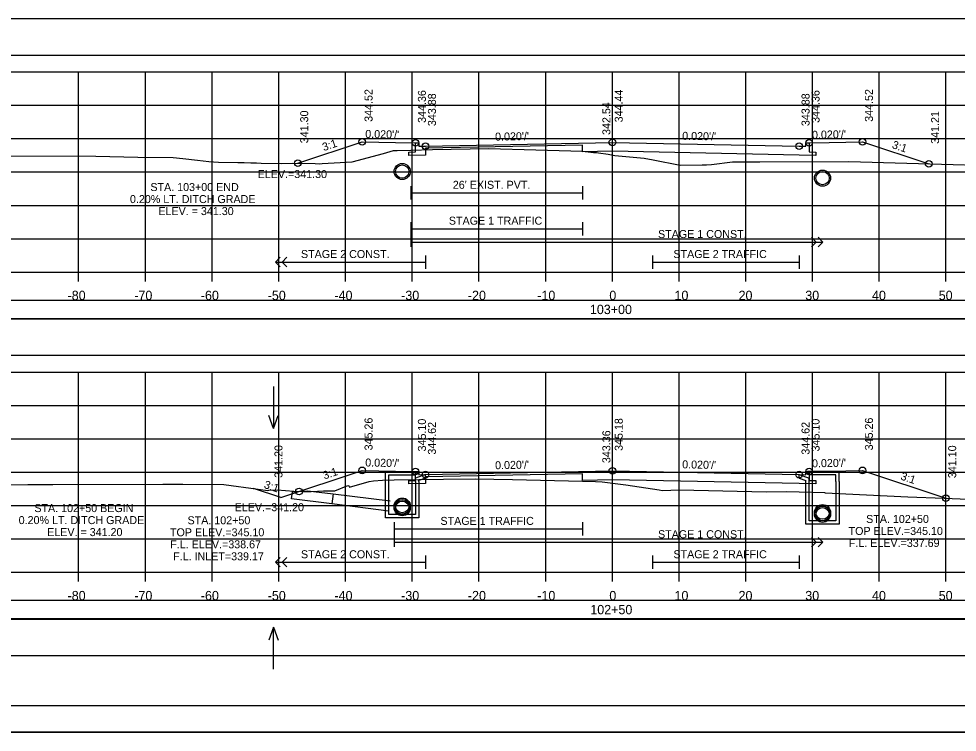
# Model space of a CAD drawing. Extents: x 1368122 to 1710785, y 373130 to 557566.
# Drawn here: x 1368599.9 to 1368740.6, y 373770.3 to 373877.3 of the extents above; entities that cross this region are included whole.
import ezdxf

# ---------------------------------------------------------------- set-up
doc = ezdxf.new("R2010")
doc.units = 0
for name, color, linetype in [('R_Alt Surface', 7, 'Continuous'), ('R_Axis', 7, 'Continuous'), ('R_Axis Annot', 7, 'Continuous'), ('R_Border', 7, 'Continuous'), ('R_Exist Surface', 7, 'Continuous'), ('R_Fin Surface', 7, 'Continuous'), ('R_Grid', 7, 'Continuous'), ('R_No Plot', 7, 'Continuous'), ('R_Striping', 7, 'Continuous'), ('R_Water', 7, 'Continuous'), ('R_Water Annot', 7, 'Continuous'), ('R_Xsect Elev', 7, 'Continuous'), ('R_Xsect Slope', 7, 'Continuous')]:
    doc.layers.add(name, color=color, linetype=linetype)

msp = doc.modelspace()

# ---------------------------------------------------------------- linework, layer by layer
at = {"layer": 'R_Alt Surface'}
for points in [[(1368539.73, 373871.85), (1368838.03, 373871.85), (1368838.03, 373877.26), (1368539.73, 373877.26)], [(1368539.73, 373832.37), (1368838.03, 373832.37), (1368838.03, 373835.08), (1368539.73, 373835.08)], [(1368539.73, 373826.85), (1368838.03, 373826.85), (1368838.03, 373832.26), (1368539.73, 373832.26)], [(1368539.73, 373787.37), (1368838.03, 373787.37), (1368838.03, 373790.08), (1368539.73, 373790.08)], [(1368539.73, 373781.85), (1368838.03, 373781.85), (1368838.03, 373787.26), (1368539.73, 373787.26)]]:
    msp.add_lwpolyline(points, close=True, dxfattribs=at)
for points in [[(1368718.38, 373858.68), (1368718.38, 373857.33), (1368719.38, 373857.31), (1368719.38, 373856.81), (1368716.88, 373856.86), (1368688.88, 373857.43), (1368684.42, 373857.34), (1368684.42, 373858.34), (1368660.88, 373857.87), (1368660.88, 373856.87), (1368660.88, 373856.86), (1368658.38, 373856.81), (1368658.38, 373857.31), (1368659.38, 373857.33), (1368659.38, 373858.68)], [(1368658.66, 373852.2), (1368658.66, 373850.2)], [(1368684.42, 373852.2), (1368684.42, 373850.2)], [(1368658.66, 373851.2), (1368684.42, 373851.2)], [(1368718.38, 373809.43), (1368718.38, 373808.08), (1368719.38, 373808.06), (1368719.38, 373807.56), (1368716.88, 373807.61), (1368688.88, 373808.17), (1368684.39, 373808.09), (1368684.39, 373809.09), (1368660.88, 373808.62), (1368660.88, 373807.62), (1368660.88, 373807.61), (1368658.38, 373807.56), (1368658.38, 373808.06), (1368659.38, 373808.08), (1368659.38, 373809.43)]]:
    msp.add_lwpolyline(points, dxfattribs=at)
at = {"layer": 'R_Axis'}
for p, q in [((1368538.88, 373839.32), (1368838.88, 373839.32)), ((1368608.88, 373837.92), (1368608.88, 373839.32)), ((1368618.88, 373837.92), (1368618.88, 373839.32)), ((1368628.88, 373837.92), (1368628.88, 373839.32)), ((1368638.88, 373837.92), (1368638.88, 373839.32)), ((1368648.88, 373837.92), (1368648.88, 373839.32)), ((1368658.88, 373837.92), (1368658.88, 373839.32)), ((1368668.88, 373837.92), (1368668.88, 373839.32)), ((1368678.88, 373837.92), (1368678.88, 373839.32)), ((1368688.88, 373837.92), (1368688.88, 373839.32)), ((1368698.88, 373837.92), (1368698.88, 373839.32)), ((1368708.88, 373837.92), (1368708.88, 373839.32)), ((1368718.88, 373837.92), (1368718.88, 373839.32)), ((1368728.88, 373837.92), (1368728.88, 373839.32)), ((1368738.88, 373837.92), (1368738.88, 373839.32)), ((1368538.88, 373794.32), (1368838.88, 373794.32)), ((1368608.88, 373792.92), (1368608.88, 373794.32)), ((1368618.88, 373792.92), (1368618.88, 373794.32)), ((1368628.88, 373792.92), (1368628.88, 373794.32)), ((1368638.88, 373792.92), (1368638.88, 373794.32)), ((1368648.88, 373792.92), (1368648.88, 373794.32)), ((1368658.88, 373792.92), (1368658.88, 373794.32)), ((1368668.88, 373792.92), (1368668.88, 373794.32)), ((1368678.88, 373792.92), (1368678.88, 373794.32)), ((1368688.88, 373792.92), (1368688.88, 373794.32)), ((1368698.88, 373792.92), (1368698.88, 373794.32)), ((1368708.88, 373792.92), (1368708.88, 373794.32)), ((1368718.88, 373792.92), (1368718.88, 373794.32)), ((1368728.88, 373792.92), (1368728.88, 373794.32)), ((1368738.88, 373792.92), (1368738.88, 373794.32))]:
    msp.add_line(p, q, dxfattribs=at)
at = {"layer": 'R_Border'}
msp.add_line((1368847.06, 373774.32), (1368530.88, 373774.32), dxfattribs=at)
at = {"layer": 'R_Exist Surface'}
for points in [[(1368597.65, 373856.72), (1368611.45, 373856.68), (1368617.73, 373856.53), (1368623.03, 373856.48), (1368624.5, 373856.33), (1368626.68, 373856.07), (1368628.4, 373855.89), (1368629.09, 373855.83), (1368629.84, 373855.8), (1368632.72, 373855.76), (1368633.7, 373855.73), (1368634.7, 373855.7), (1368635.56, 373855.7), (1368636.25, 373855.66), (1368639.31, 373855.6), (1368640.99, 373855.64), (1368644.35, 373855.57), (1368644.91, 373855.56), (1368645.4, 373855.59), (1368649.86, 373855.83), (1368654.59, 373857.08), (1368656.08, 373857.52), (1368656.61, 373857.53), (1368658.66, 373857.61), (1368661.91, 373857.68), (1368670.34, 373857.86), (1368677.38, 373857.66), (1368684.42, 373857.46), (1368686.07, 373857.26), (1368686.48, 373857.23), (1368686.79, 373857.2), (1368688.23, 373856.97), (1368689.27, 373856.8), (1368693.65, 373856.37), (1368695, 373856.14), (1368699.03, 373855.33), (1368702.32, 373855.39), (1368703, 373855.4), (1368703.72, 373855.46), (1368706.89, 373855.83), (1368710.96, 373855.83), (1368724.32, 373855.9), (1368739.96, 373855.42), (1368746.85, 373855.24)], [(1368580.47, 373807.42), (1368601.24, 373807.47), (1368601.72, 373807.47), (1368605.03, 373807.47), (1368621.5, 373807.51), (1368623.01, 373807.52), (1368624.52, 373807.51), (1368630.65, 373807.48), (1368635.77, 373806.8), (1368637.24, 373806.6), (1368637.4, 373806.61), (1368638.63, 373806.7), (1368641.13, 373806.46), (1368642.47, 373806.41), (1368643.72, 373806.43), (1368645.59, 373806.51), (1368647.29, 373806.54), (1368649.24, 373807.31), (1368649.39, 373807.29), (1368649.46, 373807.06), (1368652.43, 373807.93), (1368653.08, 373808.04), (1368654.43, 373808.1), (1368656.16, 373808.17), (1368663.56, 373808.27), (1368668.3, 373808.34), (1368673.93, 373808.22), (1368684.39, 373807.98), (1368686.36, 373807.9), (1368687.34, 373807.87), (1368690.88, 373807.44), (1368695.91, 373806.68), (1368696.32, 373806.59), (1368698.95, 373806.66), (1368711.91, 373806.36), (1368714.96, 373806.42), (1368720.67, 373806.3), (1368720.79, 373806.25), (1368733.14, 373805.64), (1368738.59, 373805.44), (1368749.38, 373804.99)]]:
    msp.add_lwpolyline(points, dxfattribs=at)
for centre in [(1368657.38, 373854.39), (1368720.38, 373853.4), (1368720.38, 373803.01)]:
    msp.add_circle(centre, 1.21, dxfattribs=at)
at = {"layer": 'R_Fin Surface'}
msp.add_line((1368639.19, 373805.52), (1368635.08, 373806.89), dxfattribs=at)
for points in [[(1368641.74, 373855.63), (1368651.38, 373858.84), (1368656.38, 373858.74), (1368659.38, 373858.68), (1368659.88, 373858.68), (1368659.88, 373858.18), (1368660.88, 373858.2), (1368688.88, 373858.76), (1368716.88, 373858.2), (1368717.88, 373858.18), (1368717.88, 373858.68), (1368718.38, 373858.68), (1368721.38, 373858.74), (1368726.38, 373858.84), (1368736.29, 373855.54)], [(1368639.19, 373805.52), (1368651.38, 373809.59), (1368656.38, 373809.49), (1368659.38, 373809.43), (1368659.88, 373809.43), (1368659.88, 373808.93), (1368660.88, 373808.95), (1368688.88, 373809.51), (1368716.88, 373808.95), (1368717.88, 373808.93), (1368717.88, 373809.43), (1368718.38, 373809.43), (1368721.38, 373809.49), (1368726.38, 373809.59), (1368738.86, 373805.43)]]:
    msp.add_lwpolyline(points, dxfattribs=at)
at = {"layer": 'R_Grid'}
for p, q in [((1368538.88, 373869.32), (1368838.88, 373869.32)), ((1368608.88, 373839.32), (1368608.88, 373869.32)), ((1368618.88, 373839.32), (1368618.88, 373869.32)), ((1368628.88, 373839.32), (1368628.88, 373869.32)), ((1368638.88, 373839.32), (1368638.88, 373869.32)), ((1368648.88, 373839.32), (1368648.88, 373869.32)), ((1368658.88, 373839.32), (1368658.88, 373869.32)), ((1368668.88, 373839.32), (1368668.88, 373869.32)), ((1368678.88, 373839.32), (1368678.88, 373869.32)), ((1368688.88, 373839.32), (1368688.88, 373869.32)), ((1368698.88, 373839.32), (1368698.88, 373869.32)), ((1368708.88, 373839.32), (1368708.88, 373869.32)), ((1368718.88, 373839.32), (1368718.88, 373869.32)), ((1368728.88, 373839.32), (1368728.88, 373869.32)), ((1368738.88, 373839.32), (1368738.88, 373869.32)), ((1368538.88, 373864.32), (1368838.88, 373864.32)), ((1368538.88, 373859.32), (1368838.88, 373859.32)), ((1368538.88, 373854.32), (1368838.88, 373854.32)), ((1368538.88, 373849.32), (1368838.88, 373849.32)), ((1368538.88, 373844.32), (1368838.88, 373844.32)), ((1368538.88, 373839.32), (1368838.88, 373839.32)), ((1368538.88, 373824.32), (1368838.88, 373824.32)), ((1368608.88, 373794.32), (1368608.88, 373824.32)), ((1368618.88, 373794.32), (1368618.88, 373824.32)), ((1368628.88, 373794.32), (1368628.88, 373824.32)), ((1368638.88, 373794.32), (1368638.88, 373824.32)), ((1368648.88, 373794.32), (1368648.88, 373824.32)), ((1368658.88, 373794.32), (1368658.88, 373824.32)), ((1368668.88, 373794.32), (1368668.88, 373824.32)), ((1368678.88, 373794.32), (1368678.88, 373824.32)), ((1368688.88, 373794.32), (1368688.88, 373824.32)), ((1368698.88, 373794.32), (1368698.88, 373824.32)), ((1368708.88, 373794.32), (1368708.88, 373824.32)), ((1368718.88, 373794.32), (1368718.88, 373824.32)), ((1368728.88, 373794.32), (1368728.88, 373824.32)), ((1368738.88, 373794.32), (1368738.88, 373824.32)), ((1368538.88, 373819.32), (1368838.88, 373819.32)), ((1368538.88, 373814.32), (1368838.88, 373814.32)), ((1368538.88, 373809.32), (1368838.88, 373809.32)), ((1368538.88, 373804.32), (1368838.88, 373804.32)), ((1368538.88, 373799.32), (1368838.88, 373799.32)), ((1368538.88, 373794.32), (1368838.88, 373794.32))]:
    msp.add_line(p, q, dxfattribs=at)
at = {"layer": 'R_No Plot'}
msp.add_line((1368518.48, 373770.34), (1368851.81, 373770.34), dxfattribs=at)
for points in [[(1368518.47, 373983.68), (1368851.81, 373983.68), (1368851.81, 373770.34), (1368518.47, 373770.34)], [(1368764.8, 373979.78), (1368784.42, 373979.78), (1368784.42, 373969.9), (1368800.53, 373969.9), (1368823.73, 373969.9), (1368823.85, 373941.75), (1368847.06, 373941.75), (1368847.06, 373774.32), (1368530.88, 373774.32), (1368530.88, 373979.78)]]:
    msp.add_lwpolyline(points, close=True, dxfattribs=at)
for centre, radius in [((1368651.38, 373858.84), 0.5), ((1368659.38, 373858.68), 0.5), ((1368688.88, 373858.76), 0.5), ((1368718.38, 373858.68), 0.5), ((1368726.38, 373858.84), 0.5), ((1368660.88, 373858.2), 0.5), ((1368716.88, 373858.2), 0.5), ((1368641.74, 373855.63), 0.5), ((1368736.29, 373855.54), 0.5), ((1368651.38, 373809.59), 0.5), ((1368659.38, 373809.43), 0.5), ((1368688.88, 373809.51), 0.5), ((1368718.38, 373809.43), 0.5), ((1368726.38, 373809.59), 0.5), ((1368660.88, 373808.95), 0.5), ((1368716.88, 373808.95), 0.5), ((1368641.91, 373806.43), 0.5), ((1368738.86, 373805.43), 0.5), ((1368657.38, 373804.24), 1.21), ((1368657.38, 373803.99), 1.21), ((1368720.38, 373803.26), 1.21)]:
    msp.add_circle(centre, radius, dxfattribs=at)
at = {"layer": 'R_Striping'}
for p, q in [((1368719.42, 373843.82), (1368718.71, 373844.53)), ((1368718.71, 373843.12), (1368719.42, 373843.82)), ((1368720.42, 373843.82), (1368719.71, 373844.53)), ((1368719.71, 373843.12), (1368720.42, 373843.82)), ((1368638.38, 373840.82), (1368639.09, 373841.53)), ((1368638.38, 373840.82), (1368660.88, 373840.82)), ((1368639.09, 373840.12), (1368638.38, 373840.82)), ((1368639.38, 373840.82), (1368640.09, 373841.53)), ((1368640.09, 373840.12), (1368639.38, 373840.82)), ((1368719.42, 373798.82), (1368718.71, 373799.53)), ((1368718.71, 373798.12), (1368719.42, 373798.82)), ((1368720.42, 373798.82), (1368719.71, 373799.53)), ((1368719.71, 373798.12), (1368720.42, 373798.82)), ((1368638.38, 373795.82), (1368639.09, 373796.53)), ((1368638.38, 373795.82), (1368660.88, 373795.82)), ((1368639.09, 373795.12), (1368638.38, 373795.82)), ((1368639.38, 373795.82), (1368640.09, 373796.53)), ((1368640.09, 373795.12), (1368639.38, 373795.82))]:
    msp.add_line(p, q, dxfattribs=at)
for points in [[(1368658.66, 373846.82), (1368658.66, 373843.12)], [(1368684.42, 373846.82), (1368684.42, 373844.82)], [(1368658.66, 373845.82), (1368684.42, 373845.82)], [(1368658.66, 373843.82), (1368720.42, 373843.82)], [(1368660.88, 373841.82), (1368660.88, 373839.82)], [(1368694.88, 373841.82), (1368694.88, 373839.82)], [(1368694.88, 373840.82), (1368716.88, 373840.82)], [(1368716.88, 373841.82), (1368716.88, 373839.82)], [(1368656.16, 373801.82), (1368656.16, 373798.12)], [(1368684.39, 373801.82), (1368684.39, 373799.82)], [(1368656.16, 373800.82), (1368684.39, 373800.82)], [(1368656.16, 373798.82), (1368720.42, 373798.82)], [(1368660.88, 373796.82), (1368660.88, 373794.82)], [(1368694.88, 373796.82), (1368694.88, 373794.82)], [(1368694.88, 373795.82), (1368716.88, 373795.82)], [(1368716.88, 373796.82), (1368716.88, 373794.82)]]:
    msp.add_lwpolyline(points, dxfattribs=at)
at = {"layer": 'R_Water'}
for p, q in [((1368654.88, 373809.43), (1368659.63, 373809.43)), ((1368654.88, 373807.93), (1368654.88, 373809.43)), ((1368655.38, 373807.93), (1368655.38, 373808.93)), ((1368655.38, 373808.93), (1368659.38, 373808.93)), ((1368659.71, 373809.26), (1368659.38, 373808.93)), ((1368660.88, 373808.95), (1368659.38, 373808.43)), ((1368659.38, 373807.93), (1368659.38, 373808.43)), ((1368659.71, 373809.26), (1368659.63, 373809.43)), ((1368660.88, 373808.42), (1368659.88, 373808.07)), ((1368716.88, 373808.95), (1368718.38, 373808.43)), ((1368716.88, 373808.42), (1368717.88, 373808.07)), ((1368718.05, 373809.26), (1368718.13, 373809.43)), ((1368718.05, 373809.26), (1368718.38, 373808.93)), ((1368722.88, 373809.43), (1368718.13, 373809.43)), ((1368722.38, 373808.93), (1368718.38, 373808.93)), ((1368718.38, 373807.93), (1368718.38, 373808.43)), ((1368722.38, 373807.93), (1368722.38, 373808.93)), ((1368722.88, 373807.93), (1368722.88, 373809.43)), ((1368659.88, 373807.93), (1368659.88, 373808.07)), ((1368717.88, 373807.93), (1368717.88, 373808.07)), ((1368655.57, 373804.98), (1368647.03, 373806.05)), ((1368655.38, 373803.49), (1368646.84, 373804.56))]:
    msp.add_line(p, q, dxfattribs=at)
for points in [[(1368660.88, 373808.42), (1368660.88, 373808.95)], [(1368716.88, 373808.42), (1368716.88, 373808.95)], [(1368659.88, 373807.93), (1368659.88, 373802.49), (1368657.38, 373802.49), (1368654.88, 373802.49), (1368654.88, 373807.93)], [(1368659.38, 373807.93), (1368659.38, 373802.99), (1368657.38, 373802.99), (1368655.38, 373802.99), (1368655.38, 373807.93)], [(1368722.88, 373807.93), (1368722.88, 373801.51), (1368720.38, 373801.51), (1368717.88, 373801.51), (1368717.88, 373807.93)], [(1368722.38, 373807.93), (1368722.38, 373802.01), (1368720.38, 373802.01), (1368718.38, 373802.01), (1368718.38, 373807.93)]]:
    msp.add_lwpolyline(points, dxfattribs=at)
msp.add_lwpolyline([(1368647.03, 373806.06), (1368646.84, 373804.57), (1368640.8, 373805.33), (1368640.93, 373806.36), (1368643.22, 373806.54)], close=True, dxfattribs=at)
for centre in [(1368657.38, 373854.39), (1368720.38, 373853.4), (1368657.38, 373804.24), (1368657.38, 373803.99), (1368720.38, 373803.26), (1368720.38, 373803.01)]:
    msp.add_circle(centre, 1, dxfattribs=at)
at = {"layer": 'R_Water Annot'}
for p, q in [((1368638.09, 373822.16), (1368638.09, 373815.87)), ((1368638.09, 373815.87), (1368637.39, 373817.8)), ((1368638.09, 373815.87), (1368638.79, 373817.8)), ((1368638.09, 373786.09), (1368637.39, 373784.16)), ((1368638.09, 373779.8), (1368638.09, 373786.09)), ((1368638.09, 373786.09), (1368638.79, 373784.16))]:
    msp.add_line(p, q, dxfattribs=at)
at = {"layer": 'R_Xsect Elev'}
for p, q in [((1368688.88, 373856.87), (1368688.88, 373866.87)), ((1368688.88, 373807.68), (1368688.88, 373817.68))]:
    msp.add_line(p, q, dxfattribs=at)

# ---------------------------------------------------------------- texts
at = {"layer": 'R_Axis Annot'}
for s, p in [('-80', (1368607.22, 373835.12)), ('-70', (1368617.22, 373835.12)), ('-60', (1368627.19, 373835.12)), ('-50', (1368637.22, 373835.12)), ('-40', (1368647.22, 373835.12)), ('-30', (1368657.22, 373835.12)), ('-20', (1368667.22, 373835.12)), ('-10', (1368677.62, 373835.12)), ('0', (1368688.42, 373835.12)), ('10', (1368698.19, 373835.12)), ('20', (1368707.79, 373835.12)), ('30', (1368717.79, 373835.12)), ('40', (1368727.79, 373835.12)), ('50', (1368737.79, 373835.12)), ('103+00', (1368685.51, 373833.02)), ('-80', (1368607.22, 373790.12)), ('-70', (1368617.22, 373790.12)), ('-60', (1368627.19, 373790.12)), ('-50', (1368637.22, 373790.12)), ('-40', (1368647.22, 373790.12)), ('-30', (1368657.22, 373790.12)), ('-20', (1368667.22, 373790.12)), ('-10', (1368677.62, 373790.12)), ('0', (1368688.42, 373790.12)), ('10', (1368698.19, 373790.12)), ('20', (1368707.79, 373790.12)), ('30', (1368717.79, 373790.12)), ('40', (1368727.79, 373790.12)), ('50', (1368737.79, 373790.12)), ('102+50', (1368685.57, 373788.02))]:
    msp.add_text(s, height=1.4, dxfattribs=at).set_placement(p)
at = {"layer": 'R_Striping'}
for s, p in [('STAGE 1 TRAFFIC', (1368664.37, 373846.42)), ('STAGE 1 CONST.', (1368695.72, 373844.42)), ('STAGE 2 CONST.', (1368642.2, 373841.42)), ('STAGE 2 TRAFFIC', (1368698.03, 373841.42)), ('STAGE 1 TRAFFIC', (1368663.11, 373801.42)), ('STAGE 1 CONST.', (1368695.72, 373799.42)), ('STAGE 2 CONST.', (1368642.2, 373796.42)), ('STAGE 2 TRAFFIC', (1368698.03, 373796.42))]:
    msp.add_text(s, height=1.2, dxfattribs=at).set_placement(p)
at = {"layer": 'R_Water'}
msp.add_text("26' EXIST. PVT.", height=1.2, dxfattribs=at).set_placement((1368664.96, 373851.8))
at = {"layer": 'R_Water Annot'}
for s, p in [('STA. 102+50', (1368625.2, 373801.51)), ('STA. 102+50', (1368726.91, 373801.71)), ('TOP ELEV.=345.10', (1368622.57, 373799.71)), ('TOP ELEV.=345.10', (1368724.28, 373799.91)), ('F.L. ELEV.=338.67', (1368622.61, 373797.91)), ('F.L. ELEV.=337.69', (1368724.31, 373798.11)), ('F.L. INLET=339.17', (1368623.04, 373796.11))]:
    msp.add_text(s, height=1.2, dxfattribs=at).set_placement(p)
at = {"layer": 'R_Xsect Elev'}
for s, p in [('344.52', (1368652.93, 373861.84)), ('344.36', (1368660.93, 373861.68)), ('343.88', (1368662.43, 373861.2)), ('344.44', (1368690.43, 373861.76)), ('343.88', (1368718.43, 373861.2)), ('344.36', (1368719.93, 373861.68)), ('344.52', (1368727.93, 373861.84)), ('342.54', (1368688.58, 373859.87)), ('341.30', (1368643.29, 373858.63)), ('341.21', (1368737.84, 373858.54)), ('345.26', (1368652.93, 373812.59)), ('345.10', (1368660.93, 373812.43)), ('344.62', (1368662.43, 373811.95)), ('345.18', (1368690.43, 373812.51)), ('344.62', (1368718.43, 373811.95)), ('345.10', (1368719.93, 373812.43)), ('345.26', (1368727.93, 373812.59)), ('343.36', (1368688.58, 373810.68)), ('341.20', (1368639.43, 373808.48)), ('341.10', (1368740.41, 373808.43))]:
    msp.add_text(s, height=1.2, rotation=90, dxfattribs=at).set_placement(p)
for s, p in [('ELEV.=341.30', (1368635.71, 373853.41)), ('STA. 103+00 END', (1368619.63, 373851.46)), ('0.20% LT. DITCH GRADE', (1368616.57, 373849.66)), ('ELEV. = 341.30', (1368620.83, 373847.86)), ('STA. 102+50 BEGIN', (1368602.24, 373803.34)), ('ELEV.=341.20', (1368632.26, 373803.47)), ('0.20% LT. DITCH GRADE', (1368599.89, 373801.54)), ('ELEV. = 341.20', (1368604.16, 373799.74))]:
    msp.add_text(s, height=1.2, dxfattribs=at).set_placement(p)
at = {"layer": 'R_Xsect Slope'}
for s, rotation, p in [("0.020'/'", 358.8542, (1368651.83, 373859.43)), ("0.020'/'", 1.1458, (1368671.31, 373859.01)), ("0.020'/'", 358.8542, (1368699.33, 373859.15)), ("0.020'/'", 1.1458, (1368718.81, 373859.29)), ('3:1', 18.4349, (1368645.62, 373857.44)), ('3:1', 341.5651, (1368730.7, 373857.92)), ("0.020'/'", 358.8542, (1368651.83, 373810.18)), ("0.020'/'", 1.1458, (1368718.81, 373810.04)), ('3:1', 18.4349, (1368645.7, 373808.22)), ("0.020'/'", 1.1458, (1368671.31, 373809.76)), ("0.020'/'", 358.8542, (1368699.33, 373809.9)), ('3:1', 341.5651, (1368731.99, 373808.24)), ('3:1', 341.5651, (1368636.56, 373806.98))]:
    msp.add_text(s, height=1.2, rotation=rotation, dxfattribs=at).set_placement(p)

doc.saveas('drawing.dxf')
